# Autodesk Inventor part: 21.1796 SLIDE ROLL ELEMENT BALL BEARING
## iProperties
Created: 2007-05
Part Number: 21.1796 SLIDE ROLL ELEMENT BALL BEARING
Material: Steel
Document SubType Name: Modeling
Designer: Andy Moles
Density: 7.85 g/cm^3
Mass: 4.34421 g
Surface Area: 5.27024 cm^2
Volume: 0.553402 cm^3
Author: Andy Moles
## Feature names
1. Extrusion1
2. Extrusion2
3. Mirror1
4. Fillet1
